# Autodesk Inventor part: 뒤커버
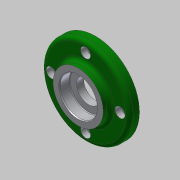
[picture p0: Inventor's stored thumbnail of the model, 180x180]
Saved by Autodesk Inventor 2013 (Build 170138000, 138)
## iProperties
Created: 2019-01
Part Number: 뒤커버
Material: 알루미늄 6061
Document SubType Name: Modeling
Designer: mduedu
Density: 1 g/cm^3
Author: mduedu
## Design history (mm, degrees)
sketch "스케치1"
  geometry: L1 (0, 0)-(6, 0); L2 (6, 0)-(6, 20); L3 (6, 20)-(0, 20); L4 (0, 20)-(0, 0); L5 (6, 0)-(14, 0); L6 (14, 0)-(14, 35); L7 (14, 35)-(6, 35); L8 (6, 35)-(6, 0); L9 (14, 0)-(19, 0); L10 (19, 0)-(19, 20); L11 (19, 20)-(14, 20); L12 (14, 20)-(14, 0)
  constraints: 24 end point, 6 parallel, 3 horizontal, 3 perpendicular
  dimensions: "d6" = 70 diameter of L7 L5; "d8" = 40 diameter of L3 L1; "d9" = 40 diameter of L11 L9; "d10" = 5 distance of L10.end L11.end; "d11" = 6 distance of L2.end L3.end; "d12" = 19 distance between parallel lines of L4 L10; "d13" = 8 distance of L6.end L7.end (derived)
revolve "회전1" sketch "스케치1" stored, may be unused: angle "d5" = 90 deg
sketch "스케치2" dims "d14" = 55
  geometry: 7 further points
  constraints: 2 coincident, 2 vertical alignment, 7 other
  dimensions: "d17" = 360 deg dimension on point (0, 0) point (0, 27.5) (derived)
sketch "스케치3"
  geometry: 4 further points
  constraints: 4 other
hole "구멍1" sketch "스케치3" at (0, 27.5), (-27.5, 0), (27.5, 0), (0, -27.5) diameter "d19" = 4.5; stored, may be unused: countersink angle "d23" = 90 deg, drill point angle "d25" = 0 deg; dims "d20" = 6, "d21" = 8, "d22" = 4.6, "d24" = 8
fillet "모깎기1" dims "d26" = 3
sketch "스케치4"
  geometry: C1 r 9.5 at (0, 0); 1 further point
  constraints: 1 centre point, 1 coincident
  dimensions: "d27" = 19 diameter of C1
extrude "돌출1" cut sketch "스케치4" stored distance "d28" = 10; taper "d29" = 0 deg
sketch "스케치5"
  geometry: C1 r 15 at (0, 0); 1 further point
  constraints: 1 centre point, 1 coincident
  dimensions: "d31" = 30 diameter of C1
extrude "돌출2" cut sketch "스케치5" distance "d32" = 8.3; taper "d33" = 0 deg
chamfer "모따기1" distance "d34" = 0.8; stored, may be unused: second distance "d35" = 2, angle "d36" = 30 deg
fillet "모깎기2" dims "d37" = 3
fillet "모깎기3" dims "d38" = 0.5
sketch "스케치6"
  geometry: C1 r 16.5 at (0, 0); 1 further point
  constraints: 1 centre point, 1 coincident
  dimensions: "d39" = 33 diameter of C1
extrude "돌출3" cut sketch "스케치6" distance "d40" = 5; taper "d41" = 0 deg
fillet "모깎기4" dims "d42" = 3
chamfer "모따기2" distance "d43" = 1; stored, may be unused: second distance "d44" = 2, angle "d45" = 30 deg
node "솔리드1"
